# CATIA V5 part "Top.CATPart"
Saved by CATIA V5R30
Part number: Part1.1
Bounding box of the stored display mesh (mm): x -50 to 50, y -25 to 25, z -20 to 10
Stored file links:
  D:\PROJECTS\CATIA V56R 2020\Resources\Parts File\c12_catia_v5_6r2020_prt\c12_catia_v5-6r2020 figr_12-22\Top.CATPart
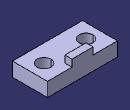
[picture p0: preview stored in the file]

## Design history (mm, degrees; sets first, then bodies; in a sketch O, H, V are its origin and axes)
Body1 (main body)
  Sketch1 on xy-plane, origin (0, 0, 0), H (1, 0, 0), V (0, 1, 0)
    line L1 (50, 25) -> (50, -25)
    line L2 (50, -25) -> (-50, -25)
    line L3 (-50, -25) -> (-50, 25)
    line L4 (-50, 25) -> (50, 25)
    circle A1 centre (-30, 0) radius 10
    point P5 (-30, 0)
    circle A2 centre (30, 0) radius 10
    length L2 = 100
    length L1 = 50
    radius A1 = 10
    distance P5 V = 30
    vertical: L1 V, L3 V
    horizontal: L2 H, L4 H
    equidistance: L1 L3 O, L2 L4 O
    coincidence: P5 H
    symmetry: A1 A2 V
  Pad1: profile Sketch1, direction (0, 0, -1), length 20
  Sketch2 on face of Pad1, origin (0, 0, 0), H (1, 0, 0), V (0, 1, 0)
    line L1 (-15, 25) -> (15, 25)
    line L2 (15, 25) -> (15, 15)
    line L3 (15, 15) -> (-15, 15)
    line L4 (-15, 15) -> (-15, 25)
    reference projected line E1 (50, 25) -> (-50, 25) from edge [face of Pad1 | face of Pad1]
    length L1 = 30
    distance L4 V = 15
    length L2 = 10
    horizontal: L1 H, L3 H
    vertical: L2 V, L4 V
    coincidence: L1 E1
  Pad2: profile Sketch2, direction (0, 0, 1), length 10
